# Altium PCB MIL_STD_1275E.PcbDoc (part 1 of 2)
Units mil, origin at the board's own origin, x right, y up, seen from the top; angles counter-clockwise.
Board outline 4000 x 3000 mil, 4 copper layers (Top Layer 1, GND, Signal Layer, Bottom Layer 1), stack 61.2 mil thick; 67 components, 20 nets, 127 pads, 432 vias.
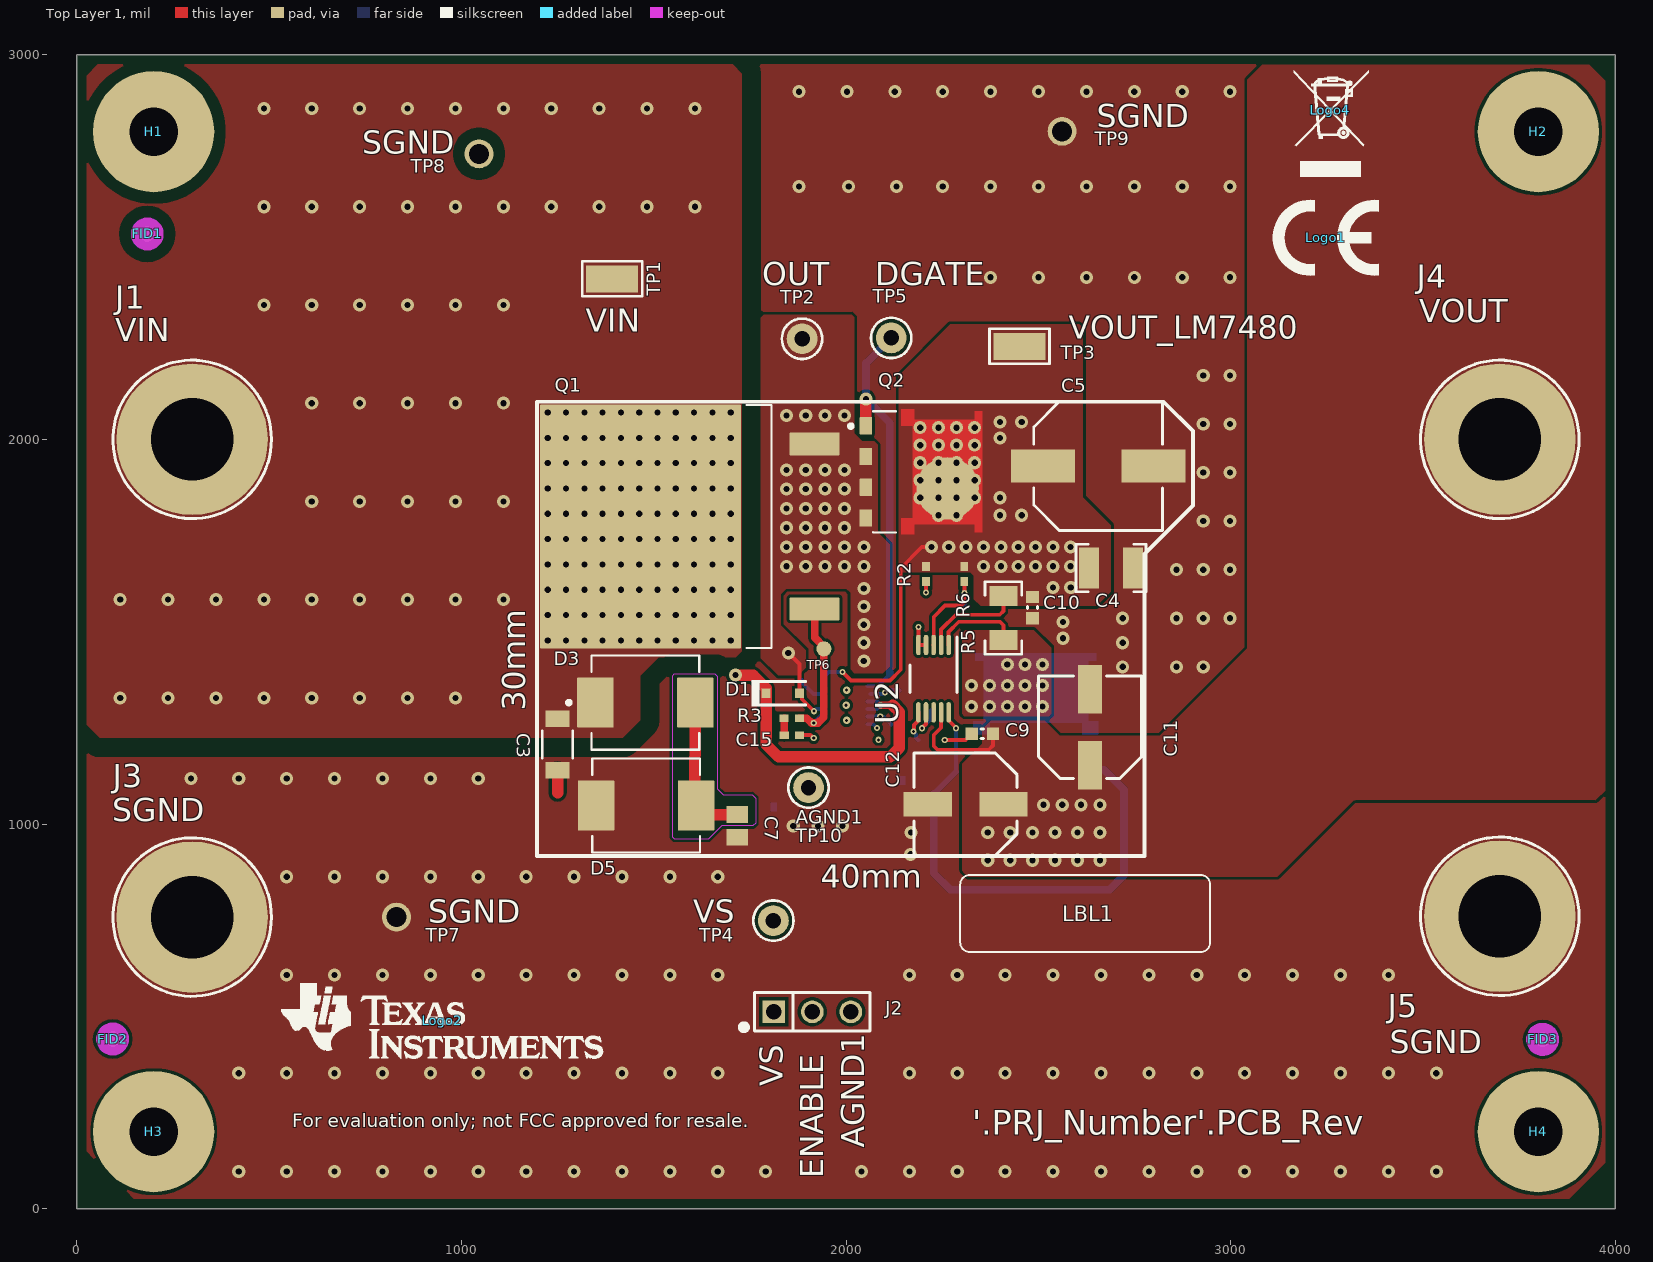
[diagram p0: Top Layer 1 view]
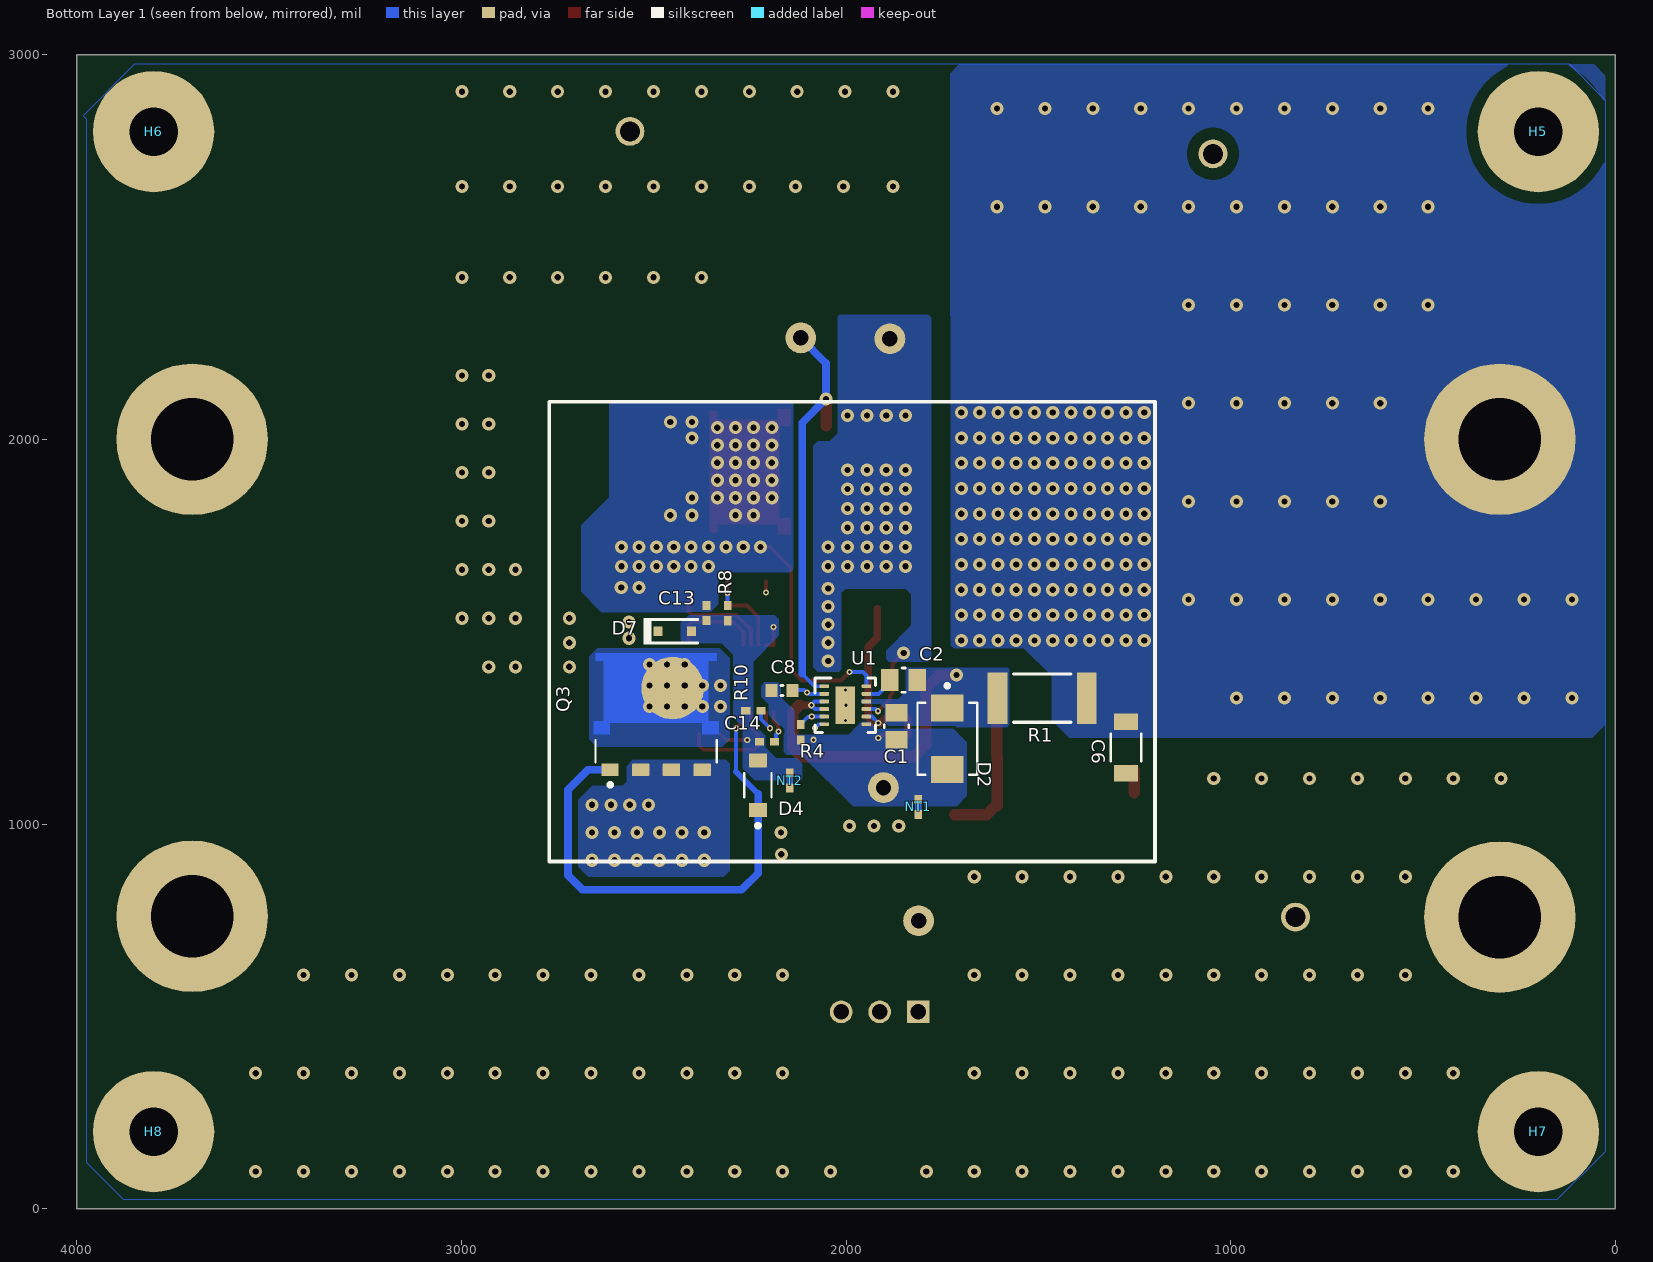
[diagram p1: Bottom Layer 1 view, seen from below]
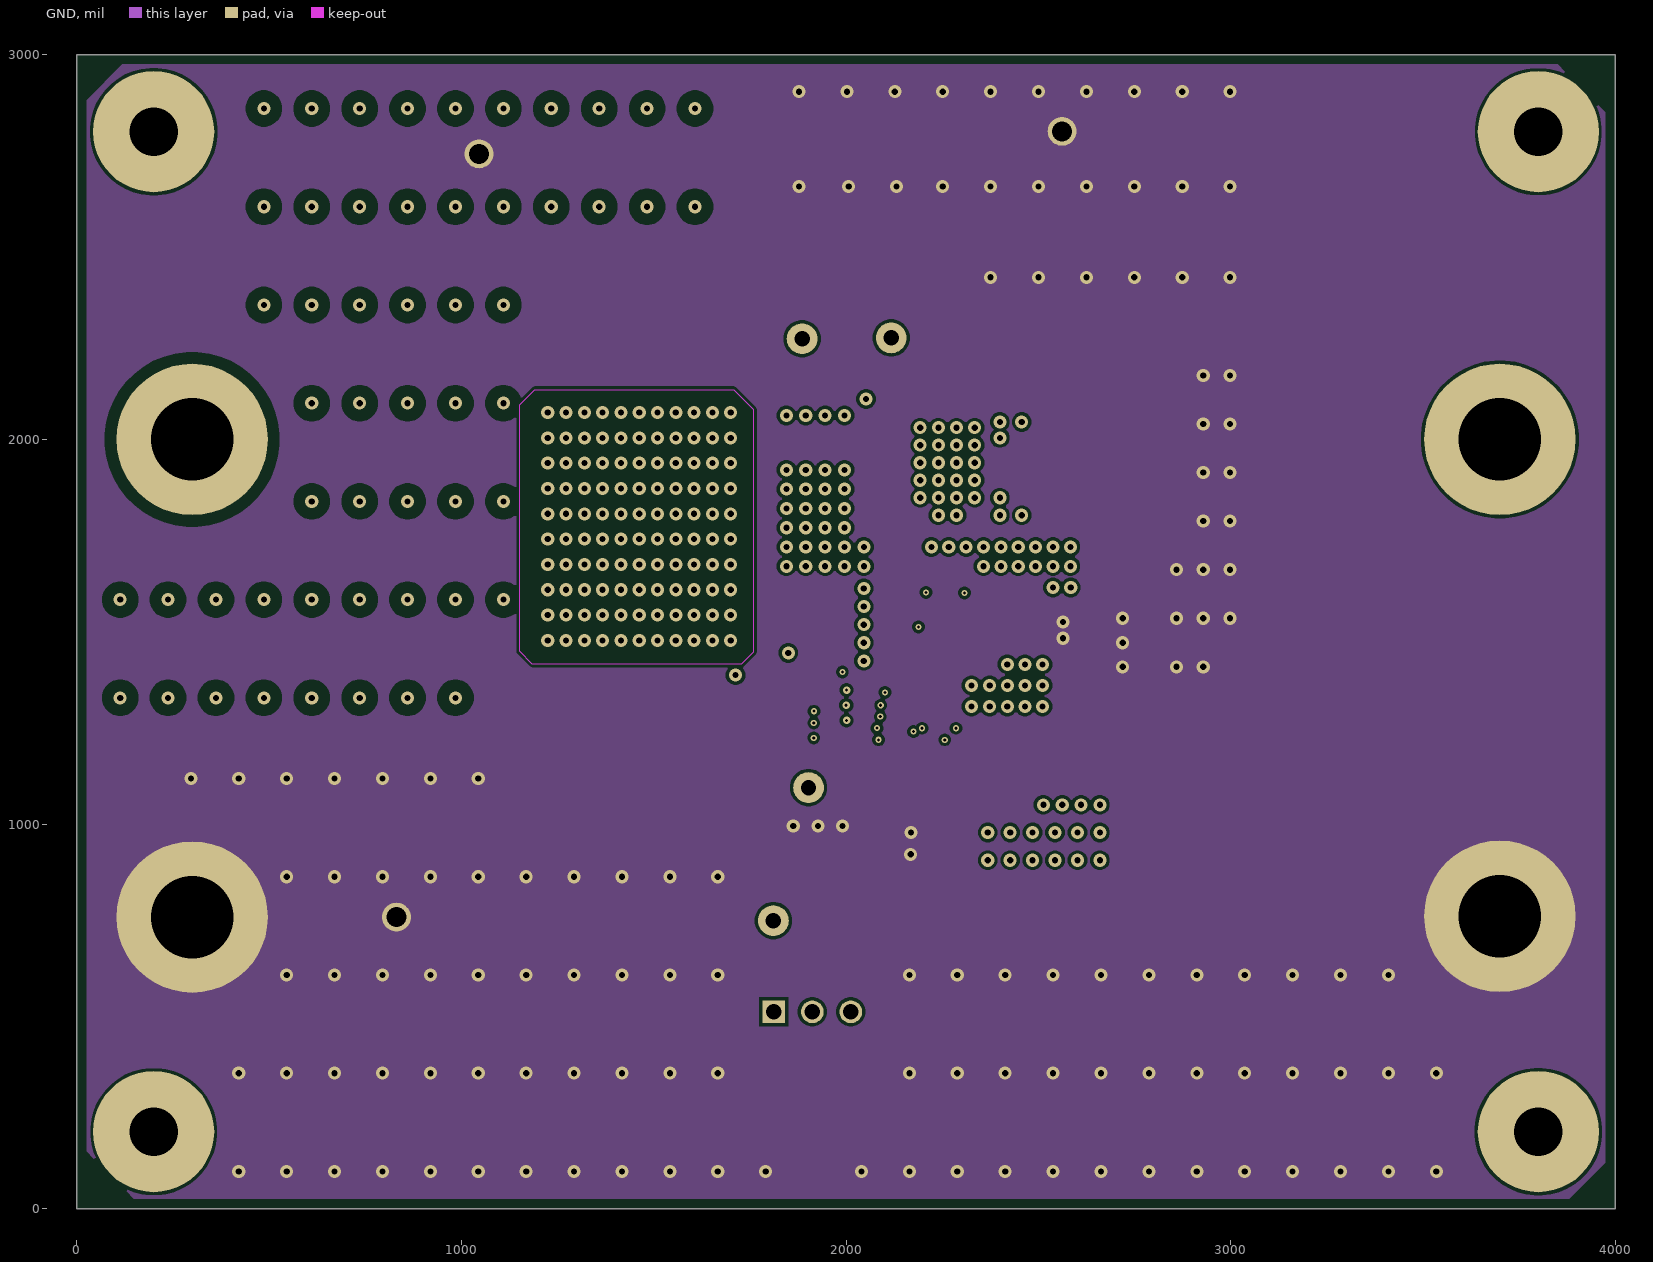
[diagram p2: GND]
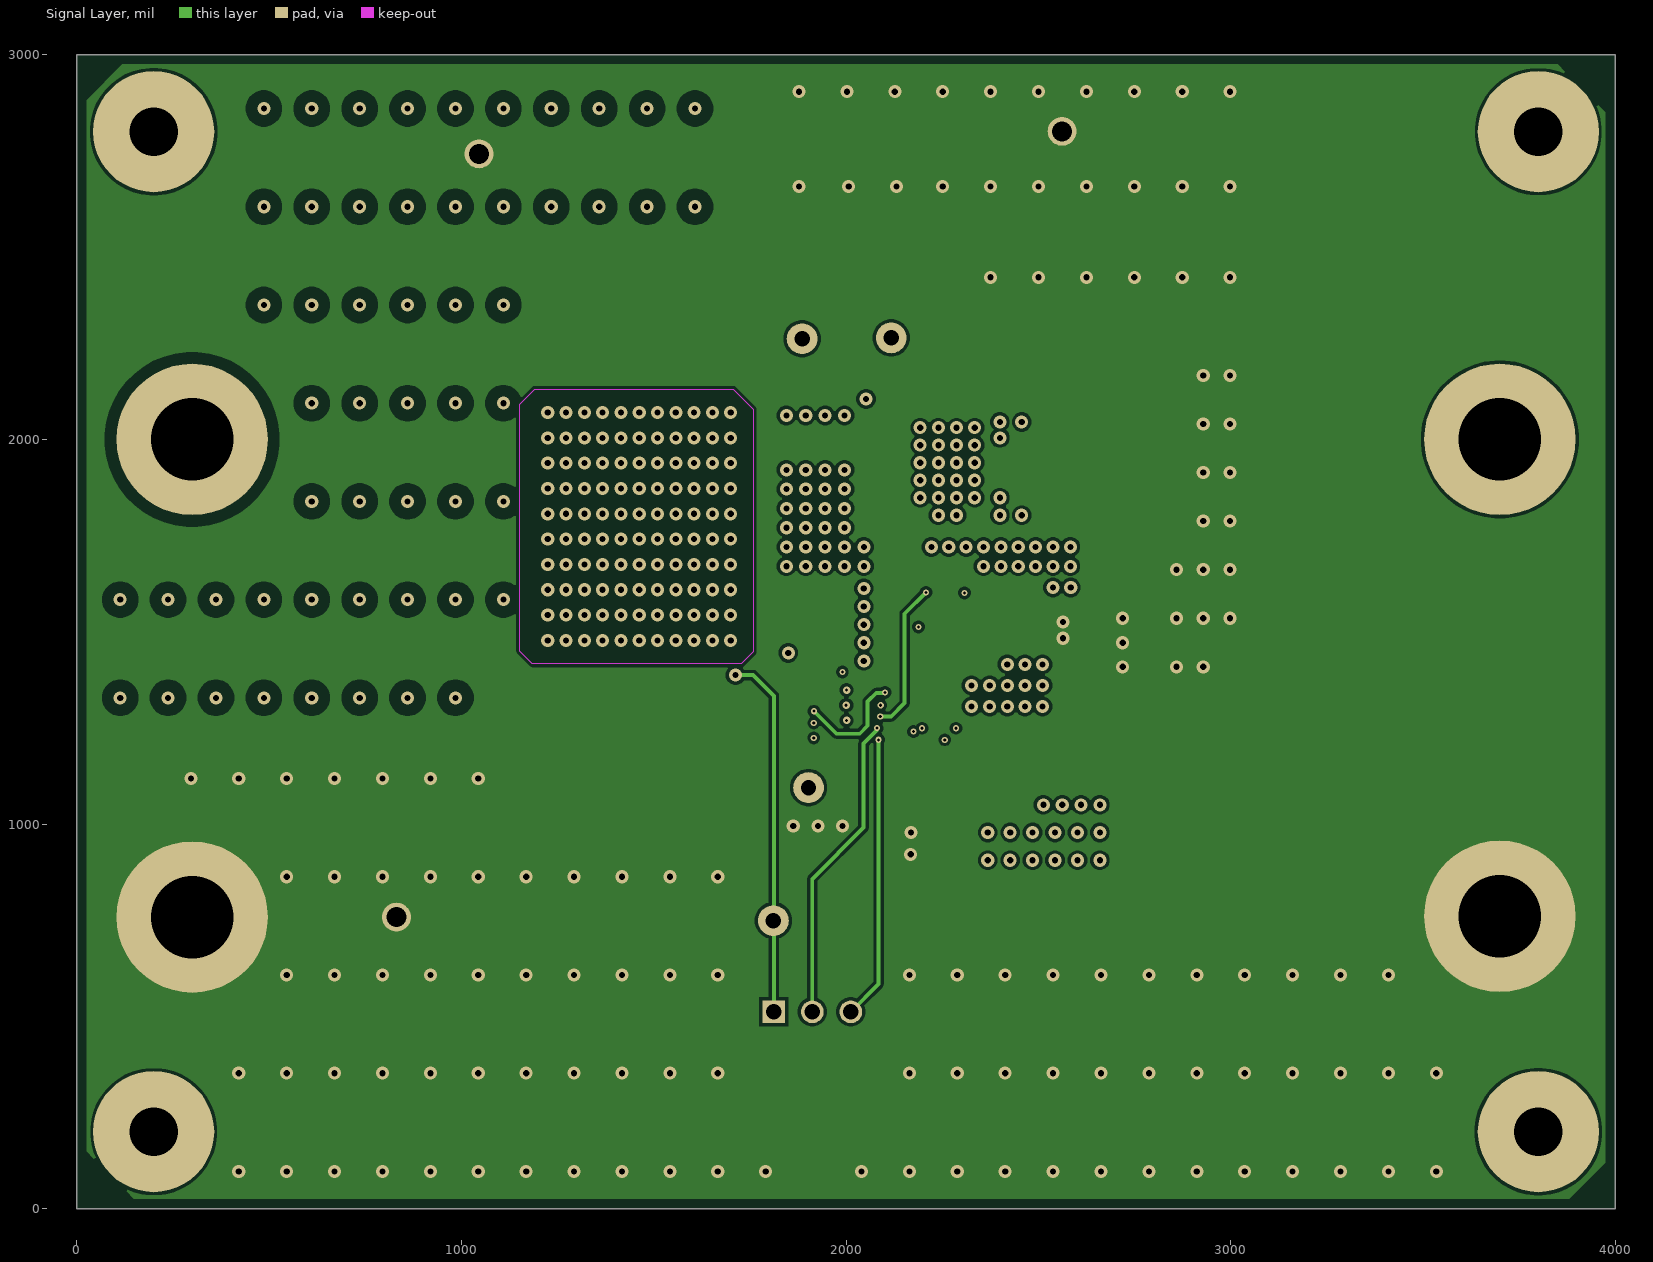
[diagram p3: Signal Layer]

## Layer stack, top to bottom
Top Solder: solder mask 0.4, Solder Resist, Dk 3.5
Top Layer 1: signal copper 1.378
Dielectric 1: prepreg 2.8, PP-006, Dk 4.1
GND: signal copper 1.4
Dielectric1: core 50.044, FR-4 High Tg, Dk 4.8
Signal Layer: signal copper 1.4
Dielectric 2: prepreg 2.8, PP-006, Dk 4.1
Bottom Layer 1: signal copper 1.378
Bottom Solder: solder mask 0.4, Solder Resist, Dk 3.5

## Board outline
0,0 4000,0 4000,3000 0,3000

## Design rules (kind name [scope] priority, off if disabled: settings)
AcuteAngle [All] p1: minimum=4.50000000000000E+0001 checktracksonly=FALSE
AssemblyTestPointUsage [All] p1: valid=2
BoardOutlineClearance BoardOutlineClearance_MountingHoles [OnCopper and InComponentClass('Mounting Holes')] p1: gap=39.37 ignorepadtopadclearanceinfootprint=FALSE
BoardOutlineClearance BoardOutlineClearance_Poly [OnCopper and IsPoly] p2: gap=25 ignorepadtopadclearanceinfootprint=FALSE
BoardOutlineClearance [OnCopper and Not InComponentClass('Logo') and not InComponentClass('FiducialMark') and not InRegion(1000,500,4000,800) and not InPoly] p3: gap=75 ignorepadtopadclearanceinfootprint=FALSE
Clearance Clear_Vin [InNet('VIN')] p1: gap=30 ignorepadtopadclearanceinfootprint=TRUE except(50: Fill-Fill Fill-Poly Fill-Region Poly-Poly Poly-Region Region-Region)
Clearance Clearance_MH [InPadClass('MH')] p2: gap=20 ignorepadtopadclearanceinfootprint=TRUE
Clearance Clearance_Keepouts [((IsTrack Or IsArc) And Not InPoly) And IsFree and IsKeepOut vs ((IsTrack Or IsArc) And Not InPoly) And IsFree and IsKeepOut] p3: gap=0 ignorepadtopadclearanceinfootprint=FALSE
Clearance Clearance_Poly [InPolygon] p4: gap=8 ignorepadtopadclearanceinfootprint=TRUE
Clearance Clearance_FiducialMark [IsKeepOut and InComponentClass('FiducialMark') vs IsPad and InComponentClass('FiducialMark')] p5: gap=0 ignorepadtopadclearanceinfootprint=FALSE
Clearance [All] p6: gap=8 ignorepadtopadclearanceinfootprint=TRUE except(20: Fill-Fill Fill-Poly Fill-Region Poly-Poly Poly-Region Region-Region)
ComponentClearance ComponentClearance_MountingHoles_FiducialMarks [InComponentClass('Mounting Holes') vs InComponentClass('FiducialMark')] p1: gap=50 collisioncheckmode=3 verticalgap=10 showdistances=FALSE
ComponentClearance ComponentClearance_Shunt [InComponentClass('Header') vs InComponentClass('Shunt')] p2: gap=0 collisioncheckmode=3 verticalgap=0 showdistances=FALSE
ComponentClearance ComponentClearance_Logo [InComponentClass('Logo')] p3: gap=50 collisioncheckmode=3 verticalgap=10 showdistances=FALSE
ComponentClearance ComponentClearance_ScrewToNut [(HasFootprint('NY PMS 440 0025 PH')) vs (HasFootprint('Keystone_1902C'))] p4: gap=5 collisioncheckmode=3 verticalgap=10 showdistances=FALSE
ComponentClearance ComponentClearance_MountingHoles [InComponentClass('Mounting Holes')] p5: gap=250 collisioncheckmode=3 verticalgap=100000 showdistances=FALSE
ComponentClearance ComponentClearance_SmallPassives [HasFootprint('0201*') or HasFootprint('0402*') or HasFootprint('0508') or HasFootprint('0603*') or HasFootprint('0612') or HasFootprint('0805*') or HasFootprint('0815*') or HasFootprint('0830*') or HasFootprint('1206*') or HasFootprint('1210*') or HasFootprint('1808*') or HasFootprint('1812*') or HasFootprint('1825*') or HasFootprint('2010*') or HasFootprint('2220*') or HasFootprint('2225*') or HasFootprint('2512*') or HasFootprint('2728*') or HasFootprint('3518*') vs HasFootprint('0201*') or HasFootprint('0402*') or HasFootprint('0508') or HasFootprint('0603*') or HasFootprint('0612') or HasFootprint('0805*') or HasFootprint('0815*') or HasFootprint('0830*') or HasFootprint('1206*') or HasFootprint('1210*') or HasFootprint('1808*') or HasFootprint('1812*') or HasFootprint('1825*') or HasFootprint('2010*') or HasFootprint('2220*') or HasFootprint('2225*') or HasFootprint('2512*') or HasFootprint('2728*') or HasFootprint('3518*')] p6: gap=14.96 collisioncheckmode=3 verticalgap=10 showdistances=FALSE
ComponentClearance ComponentClearance_THtoSMT [IsThruComponent vs IsSMTComponent] p7: gap=40 collisioncheckmode=3 verticalgap=30 showdistances=FALSE
ComponentClearance ComponentClearance_THtoTH [IsThruComponent vs IsThruComponent] p8: gap=30 collisioncheckmode=3 verticalgap=30 showdistances=FALSE
ComponentClearance [All] p9: gap=24 collisioncheckmode=3 verticalgap=10 showdistances=FALSE
DiffPairsRouting [All] p1: maxlimit=100 minlimit=10 mostfreqgap=10 toplayer_minwidth=15 toplayer_maxwidth=15 toplayer_prefwidth=15 midlayer1_minwidth=15 midlayer1_maxwidth=15 midlayer1_prefwidth=15 midlayer2_minwidth=15 midlayer2_maxwidth=15 midlayer2_prefwidth=15 bottomlayer_minwidth=15 bottomlayer_maxwidth=15 bottomlayer_prefwidth=15 maxuncoupledlength=1000
FabricationTestPointUsage TestPointUsage [All] p1: valid=2 allowmultiple=FALSE
FabricationTestpoint Testpoint [All] p1: side=3 testpointundercomponent=TRUE minsize=40 maxsize=100 preferedsize=60 minholesize=0 maxholesize=40 preferedholesize=32 testpointgrid=1 allowsidetop=TRUE allowsidebottom=TRUE usegrid=TRUE gridtolerance=0.01
FanoutControl Fanout_LCC [IsLCC] p1: bgadir=Out bgaviamode=Centered fanoutstyle=Auto fanoutdirection=Alternating viagrid=1 // Fanout_LCC (Default Rule)
FanoutControl Fanout_BGA [IsBGA] p2: bgadir=Out bgaviamode=Centered fanoutstyle=Auto fanoutdirection=Alternating viagrid=1 // Fanout_BGA (Default Rule)
FanoutControl Fanout_Default [All] p4: bgadir=Out bgaviamode=Centered fanoutstyle=Auto fanoutdirection=Alternating viagrid=1 // Fanout_Default (Default Rule)
FanoutControl Fanout_Small [(CompPinCount < 5)] p5: bgadir=Out bgaviamode=Centered fanoutstyle=Auto fanoutdirection=OutThenIn viagrid=1 // Fanout_Small (Default Rule)
HoleSize [All] p1: absolutevalues=TRUE maxlimit=251 minlimit=7.87 maxpercent=80.000 minpercent=20.000
MinimumAnnularRing MinimumAnnularRing_ThermalPadVias [IsVia and InAnyComponent] p1: minimumring=5.91
MinimumAnnularRing [All] p2: minimumring=4
MinimumSolderMaskSliver MinimumSolderMaskSliver_Logo [InComponentClass('Logo') vs InComponentClass('Logo')] p1: minsoldermaskwidth=0.7
MinimumSolderMaskSliver [All] p2: minsoldermaskwidth=3.94
PlaneConnect [All] p1: planeconnectstyle=Direct reliefexpansion=10 reliefentries=4 reliefconductorwidth=10 reliefairgap=10
PolygonConnect [All] p1: connectstyle=Direct reliefconductorwidth=10 reliefentries=4 polygonreliefangle="90 Angle" airgapwidth=10
RoutingVias ThermalPadVias [IsVia and InAnyComponent] p1: holewidth=7.87 width=19.68 viastyle="Through Hole" minholewidth=7.87 minwidth=19.68 maxholewidth=12.99 maxwidth=23.62
RoutingVias [All] p2: holewidth=16 width=34 viastyle="Through Hole" minholewidth=8 minwidth=16 maxholewidth=40 maxwidth=65
ShortCircuit U1 [InPadClass('U1') vs Hole] p1: allowed=TRUE
ShortCircuit [All] p2: allowed=FALSE
SilkToBoardRegionClearance [Not ((IsComment or IsDesignator) And (Hide <> 'False')) and not InRegion(1000,500,4000,800)] p1:
SilkToSilkClearance SilkToSilkClearance_Pb-FreeLogo [(HasFootprint('Pb-Free_Overlay_Medium') OR HasFootprint('Pb-Free_Overlay_Small')) vs (HasFootprint('Pb-Free_Overlay_Medium') OR HasFootprint('Pb-Free_Overlay_Small'))] p1: silktosilkclearance=0
SilkToSilkClearance [All] p2: silktosilkclearance=3.94
SilkToSolderMaskClearance SilkToComponentPadClearance [(IsPad or IsFill or IsRegion) and InAnycomponent] p1: minsilkscreentomaskgap=2 clearancetoexposedcopper=TRUE
SilkToSolderMaskClearance "Silk to Solder Mask Opening" [All] p2: minsilkscreentomaskgap=2 clearancetoexposedcopper=FALSE
SolderMaskExpansion SolderMaskExpansion_via [IsVia] p1: expansion=0 istentingtop=FALSE
SolderMaskExpansion SolderMaskExpansion_pads [ispad] p2: expansion=1.97 istentingtop=FALSE
UnRoutedNet [All] p1: checkbadconnections=TRUE
Width [All] p1: maxlimit=100 minlimit=6 preferedwidth=10 checkconnectedcopper=TRUE
13 further rules are at their usual default settings.

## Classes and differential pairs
component class MIL_STD_1275E_LM74800_Clamping_Circuit: C1 C2 C3 C4 C5 C6 C7 C8 C15 D1 D2 D3 D5 J1 J2 J3 NT1 Q1 Q2 R1 R2 R3 R4 TP1 TP2 TP3 TP4 TP5 TP6 TP7 TP8 TP9 TP10 U1
component class MIL_STD_1275E_LM5069_Clamping_Circuit: C9 C10 C11 C12 C13 C14 D4 D7 J4 J5 NT2 Q3 R5 R6 R8 R10 U2
component class Header: J2
component class "Mounting Holes": H1 H2 H3 H4
component class Logo: Logo2
component class MIL_STD_1275E_Hardware: FID1 FID2 FID3 H1 H2 H3 H4 H5 H6 H7 H8 LBL1 Logo1 Logo2 Logo3 Logo4
component class FiducialMark: FID1 FID2 FID3
component class Label: LBL1

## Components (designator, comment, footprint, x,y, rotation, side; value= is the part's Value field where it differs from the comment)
C1 "08051C105K4Z2A" 0805_150 1868.56,1254.28 r270 bottom value=1uF
C2 "08051C105K4Z2A" 0805_150 1850.38,1374.18 r0 bottom value=1uF
C3 "C3216X7T2W104M160AE" 1206_180 1249.99,1206.88 r270 top value=0.1uF
C4 "CMP-0009084-1" 1210_210 2688.98,1665.64 r0 top value=2.2uF
C5 "EMVE630ADA470MHA0G" CAPSMT_62_HA0 2655.81,1930.59 r0 top value=47uF
C6 "C3216X7T2W104M160AE" 1206_180 1272.17,1198.82 r270 bottom value=0.1uF
C7 "CGA4J3X7R1H105K125AB" 0805L 1717.28,995.02 r270 top value=1uF
C8 "CGA3E2X7R2A153K080AA" 0603L 2166.46,1346.98 r0 bottom value=0.015uF
C9 "C0603C104J5RACTU" 0603L 2354.46,1234.67 r180 top value=0.1uF
C10 "GRM188R72A104KA35D" 0603L 2484.67,1562.5 r270 top value=0.1uF
C11 "EEEFTH101XAP" Panasonic_D8 2634.37,1251.55 r90 top value=100uF
C12 "EEEFTH101XAP" Panasonic_D8 2311.11,1051.3 r180 top value=100uF
C13 "GRM155R72A102KA01D" 0402L 2362.74,1548.63 r90 bottom value=1000pF
C14 "GRM155R61A564KE15D" 0402L 2205.06,1214.07 r0 bottom value=0.56uF
C15 "CGA2B3X7S2A103K050BB" 0402L 1859.08,1231.17 r0 top value=0.01uF
D1 "1N4148WS-HG3-08" SOD-323 1835.46,1339.91 r0 top value=100V
D2 "SMBJ5369B-TP" FP-SMBJ5369B-TP_SMB-MFG 1736.6,1221.54 r270 bottom
D3 "SMDJ120A" FP-SMDJ120A_DO214AB-MFG 1478.3,1315.71 r0 top
D4 "SZMMSZ4715T1G" FP-SZMMSZ4715T1G_SOD123-MFG 2228.84,1100.98 r90 bottom
D5 "5.0SMDJ33CA" FP-5.0SMDJ33CA_DO214AB-MFG 1480.41,1048.09 r0 top
D7 "BAV20WS-TP" SOD-323 2445.32,1501.24 r180 bottom value=150V
FID1 "Fiducial" Fiducial10-20 183.21,2534.06 r0 top
FID2 "Fiducial" Fiducial10-20 93.21,440.98 r0 top
FID3 "Fiducial" Fiducial10-20 3811.24,439.96 r0 top
H1 "NY PMS 440 0025 PH" "NY PMS 440 0025 PH" 200,2800 r0 top
H2 "NY PMS 440 0025 PH" "NY PMS 440 0025 PH" 3800,2800 r0 top
H3 "NY PMS 440 0025 PH" "NY PMS 440 0025 PH" 200,200 r0 top
H4 "NY PMS 440 0025 PH" "NY PMS 440 0025 PH" 3800,200 r0 top
H5 "1902C" Keystone_1902C 200,2800 r180 bottom
H6 "1902C" Keystone_1902C 3800,2800 r180 bottom
H7 "1902C" Keystone_1902C 200,200 r180 bottom
H8 "1902C" Keystone_1902C 3800,200 r180 bottom
J1 "CMP-0055166-2" Keystone575-8 300,2000 r90 top
J2 "PEC03SAAN" CONN_PEC03SAAN 1912.43,511.6 r0 top
J3 "CMP-0055166-2" Keystone575-8 300,758 r90 top
J4 "CMP-0055166-2" Keystone575-8 3700,2000 r90 top
J5 "CMP-0055166-2" Keystone575-8 3700,760 r90 top
LBL1 "THT-14-423-10" Label_650x200 2621.92,767.3 r0 top
Logo1 "CE Mark" CE_Mark_5mm 3247.82,2524.21 r0 top
Logo2 "Texas Instruments" TI_Stacked_Overlay_Small 949.88,488.24 r0 top
Logo3 "FCC disclaimer" FCC_disclaimer 2350,3380 r0 top
Logo4 "WEEE logo" WEEE_Minimum 3259.19,2855.52 r0 top
NT1 "Net-Tie" NetTie_0402 1812.43,1044.24 r90 bottom net-tie
NT2 "Net-Tie" NetTie_0402 2145.93,1113.08 r90 bottom net-tie
Q1 "IXTT88N30P" FP-IXTT88N30P_TO-268AA-IPC_C 1593.59,1773.6 r90 top
Q2 "SQJQ466E-T1_GE3" "FP-SQJQ466E-T1_GE3_PowerPAK 8 x 8L-MFG" 2194.88,1915.52 r270 top
Q3 "SQJQ466E-T1_GE3" "FP-SQJQ466E-T1_GE3_PowerPAK 8 x 8L-MFG" 2493.79,1284.21 r180 bottom
R1 "HVCB2512FDD10K0" 2512_084 1489.8,1327.55 r180 bottom value=10.0k
R2 "ERJ-2RKF1003X" 0402L 2208.03,1650.32 r90 top value=100k
R3 "CRCW0402100RJNED" 0402L 1858.95,1274.97 r180 top value=100
R4 "CRCW04022K55FKED" 0402L 2117.24,1238.56 r90 bottom value=2.55k
R5 "CRF1206-FZ-R004ELF" 1206 2409.15,1535.66 r270 top value=0.004
R6 "CRCW040295K3FKED" 0402L 2307.9,1650.32 r90 top value=95.3k
R8 "CRCW040213K7FKED" 0402L 2307.9,1548.12 r90 bottom value=13.7k
R10 "CRCW040254K9FKED" 0402L 2240.88,1294.74 r180 bottom value=54.9k
TP1 "5015" Testpoint_Keystone_Miniature 1391.85,2417.46 r180 top
TP2 "5003" Keystone5003 1885.81,2261.6 r180 top
TP3 "5015" Testpoint_Keystone_Miniature 2450.88,2241.48 r180 top
TP4 "5003" Keystone5003 1811.24,748.77 r180 top
TP5 "5003" Keystone5003 2117.53,2263.8 r180 top
TP6 "TP_SM_1MM" TP_SM_1MM 1942.53,1455.45 r180 top
TP7 "CMP-0055161-1" CONN_1040 831.24,758 r90 top
TP8 "CMP-0055161-1" CONN_1040 1045.86,2742.33 r90 top
TP9 "CMP-0055161-1" CONN_1040 2561.81,2800.96 r90 top
TP10 "5001" Keystone5001 1902.53,1094.66 r180 top
U1 "PLM74800DRRRQ1" DRR0012E 2001.59,1308.76 r180 bottom
U2 "LM5069MM-2" DGS0010A_N 2227.71,1377.84 r270 top

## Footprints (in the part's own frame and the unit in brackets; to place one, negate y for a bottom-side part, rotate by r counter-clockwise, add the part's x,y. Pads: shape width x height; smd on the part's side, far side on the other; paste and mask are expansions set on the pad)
0402L [mm] "0402 from SM-752 data"
  rect 0.6x0.5 smd: 1(-0.5,0) 2(0.5,0)
  body extent -0.55,-0.3 0.55,0.3, height 0.6
0603L [mm] "0603 from SM-752 data"
  rect 0.8x0.85 smd: 1(-0.7,0) 2(0.7,0)
  silkscreen extent -0.07,-0.33 0.07,0.33, body extent -0.87,-0.47 0.87,0.47, height 1
0805_150 [mm] "0805 / 1.5 mm height"
  rect 1.15x1.45 smd: 1(-0.9,0) 2(0.9,0)
  silkscreen extent -0.1,-0.8 0.1,0.8, body extent -1.1,-0.72 1.1,0.72, height 1.5
0805L [mm] "0805 from SM-752 data"
  rect 1.1x1.4 smd: 1(-0.75,0) 2(0.75,0)
  body extent -1.1,-0.72 1.1,0.72, height 1.45
1206 [mm] "1206 from SM-752 data"
  rect 1.3x1.85 smd: 1(-1.45,0) 2(1.45,0)
  silkscreen extent -2.4,-1.21 2.4,1.21, body extent -1.7,-0.9 1.7,0.9, height 1.35
1206_180 [mm] "1206_180"
  rect 1.1x1.6 smd: 1(-1.7,0) 2(1.7,0)
  silkscreen extent -0.9,-1 0.9,1, body extent -1.75,-0.95 1.75,0.95, height 1.8
1210_210 [mm] "1210"
  rect 1.3x2.7 smd: 1(-1.45,0) 2(1.45,0)
  silkscreen extent -2.32,-1.57 2.32,1.57, body extent -1.7,-1.35 1.7,1.35, height 2.1
2512_084 [mm] "Chip Resistor, Body 6.3x3.2mm"
  rect 1.3x3.4 smd: 1(-2.95,0) 2(2.95,0)
  silkscreen extent -1.9,-1.6 1.9,1.6, body extent -3.22,-1.67 3.22,1.67, height 0.84
CAPSMT_62_HA0 [mm] "8 x 10mm:  Chemi-Con HA0"
  rect 4.2x2.2 smd: 1(-3.65,0) 2(3.65,0)
  silkscreen extent -4.25,-4.25 4.25,4.25, body extent -4.25,-4.25 4.25,4.25, height 10.5
CE_Mark_5mm [mil] "Minimum text height for CE Mark"
  silkscreen extent -138,-98 138,98
CONN_1040 [mil] "Test Point, PC  test point Terminal"
  round 75 hole 52: 1(0,0)
  body extent -55,-12 55,13, height 276
CONN_PEC03SAAN [mm] "SULLINS"
  rect 1.5x1.5 hole 1.016: 1(-2.54,0)
  round 1.5 hole 1.016: 2(0,0) 3(2.54,0)
  silkscreen extent -4.72,-1.27 3.81,1.27, body extent -3.84,-1.3 3.84,1.3, height 8.38
DGS0010A_N [mm] "TSSOP, 10-Leads, Body 3x3mm, Pitch 0.5mm, IPC Medium Density"
  oval 1.35x0.3 smd: 1(-2.225,1) 2(-2.225,0.5) 3(-2.225,0) 4(-2.225,-0.5) 5(-2.225,-1) 6(2.225,-1) 7(2.225,-0.5) 8(2.225,0) 9(2.225,0.5) 10(2.225,1)
  silkscreen extent -2.75,-1.55 0.9,1.55, body extent -2.45,-1.5 2.45,1.5, height 0.96
DRR0012E [mm] "WSON-12"
  rrect40% 0.62x0.25 smd: 1(-1.39,1.25) 2(-1.39,0.75) 3(-1.39,0.25) 4(-1.39,-0.25) 5(-1.39,-0.75) 6(-1.39,-1.25) 7(1.39,-1.25) 8(1.39,-0.75) 9(1.39,-0.25) 10(1.39,0.25) 11(1.39,0.75) 12(1.39,1.25)
  rrect8% 1.3x2.5 smd paste-1.7: 13(0,0)
  silkscreen extent -2,-1.8 2,1.8, body extent -1.5,-1.5 1.5,1.5, height 0.81
FCC_disclaimer [mil]
Fiducial10-20 [mm]
  round 1 smd mask+0.5: 1(0,0)
  Top Layer 1 keep-out circle w1.178: c0,0 r0.5
FP-5.0SMDJ33CA_DO214AB-MFG [mm]
  rrect4% 2.4x3.3 smd paste+0 mask+0: 1(-3.3,0) 2(3.3,0)
  silkscreen extent -3.55,-3.11 3.55,3.11, body extent -4.6,-3.21 4.6,3.21, height 0.25
FP-IXTT88N30P_TO-268AA-IPC_C [mm]
  rrect7% 1.5x3.3 smd paste+0 mask+0: 1(-5.45,-8.25) 3(5.45,-8.25)
  rrect1% 16.1x13.3 smd paste+0 mask+0: 4(0,3.25)
  silkscreen extent -8.03,-5.4 8.03,-3.77, body extent -8.15,-10 8.15,10, height 0.25
FP-SMBJ5369B-TP_SMB-MFG [mil]
  rrect6% 70x85 smd paste+0 mask+0: 1(-80,0) 2(80,0)
  silkscreen extent -143,-78 94,78, body extent -105,-71 105,71, height 95
FP-SMDJ120A_DO214AB-MFG [mm]
  rrect4% 2.4x3.3 smd paste+0 mask+0: 1(-3.3,0) 2(3.3,0)
  silkscreen extent -5.17,-3.11 3.55,3.11, body extent -4.6,-3.21 4.6,3.21, height 0.25
"FP-SQJQ466E-T1_GE3_PowerPAK 8 x 8L-MFG" [mm]
  rrect12% 1.15x0.82 smd paste+0 mask+0: 1(-3.045,-3.64) 2(-1.015,-3.64) 3(1.015,-3.64) 4(3.045,-3.64)
  round 4.13 smd paste+0 mask+0: 5(1.09,1.755)
  Top Layer 1 region: -4,4.05 4,4.05 4,3.55 3.45,3.55 3.45,-0.44 4.125,-0.44 4.125,-1.29 3.055,-1.29 3.055,-0.54 -3.055,-0.54 -3.055,-1.29 -4.125,-1.29 -4.125,-0.44 -3.45,-0.44 -3.45,3.55 -4,3.55 -4,4.05
  silkscreen extent -4,-4.75 4,-1.67, body extent -4.23,-4.15 4.23,4.15, height 0.25
FP-SZMMSZ4715T1G_SOD123-MFG [mil]
  rrect11% 36x48 smd paste+0 mask+0: 1(-64.5,0) 2(64.5,0)
  silkscreen extent -110,-35 32,35, body extent -72,-31 72,31, height 53
Keystone575-8 [mm] "Banana Jack"
  round 10 hole 5.45: 1(0,0)
  silkscreen extent -5.23,-5.23 5.23,5.23, body extent -3.92,-3.94 3.95,3.94, height 2.36
Keystone5001 [mil] "For Keystone 500x miniature loop terminals"
  round 80 hole 40: 1(0,0)
  silkscreen extent -52,-52 52,52, body extent -49,-49 49,49, height 182
Keystone5003 [mil] "For Keystone 500x miniature loop terminals"
  round 80 hole 40: 1(0,0)
  silkscreen extent -52,-52 52,52, body extent -49,-49 49,49, height 182
Keystone_1902C [mil] "Hex Standoff, 4-40 threaded, nylon"
  round 1 on Mech4: 0(0,0)
  body extent -145,-126 146,126, height 501
Label_650x200 [mil] "Thermal Transfer Label"
  round 1 on Mech13: 0(0,0)
  silkscreen extent -325,-100 325,100, body extent -325,-100 325,100, height 1
NetTie_0402 [mm] "Net Tie 0402 size"
  rect 0.6x0.5 smd paste-0.5: 1(-0.5,0) 2(0.5,0)
  Top Layer 1 region: -0.279,0.203 0.279,0.203 0.279,-0.203 -0.279,-0.203
"NY PMS 440 0025 PH" [mm] "4-40 nylon screw and mounting hole"
  round 8 hole 3.2: 1(0,0)
  body extent -3.3,-3.3 3.3,3.3, height 2.69
Panasonic_D8 [mm] "SMD, 2-Leads, Dia 6.3mm"
  rect 3.2x1.6 smd: 1(-2.5,0) 2(2.5,0)
  silkscreen extent -3.4,-3.4 3.4,3.4, body extent -3.4,-3.4 3.4,3.4, height 8.01
SOD-323 [mm] "NXP recommended land pattern"
  rect 0.6x0.6 smd paste-0.05: 1(-1.1,0) 2(1.1,0)
  silkscreen extent -2.06,-0.86 1.53,0.86, body extent -1.3,-0.67 1.3,0.68, height 1.1
Testpoint_Keystone_Miniature [mil] "Miniature SMT test point"
  rect 135x70 smd: 1(0,0)
  silkscreen extent -78,-46 78,45, body extent -52,-20 52,20, height 61
TI_Stacked_Overlay_Small [mil]
  silkscreen extent -418,-98 418,98
TP_SM_1MM [mm] "1mm Test Point, SMT"
  round 1 smd paste-0.5: 1(0,0)
WEEE_Minimum [mil] "WEEElie bin"
  silkscreen extent -95,-172 99,104

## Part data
C1 C2: library part CMP-0861070-1, "CAP, CERM, 1 µF, 100 V,+/- 10%, X7R, AEC-Q200 Grade 1, 0805", Cap_Case=0805, Manufacturer=AVX, TempCo=X7R, Tolerance_%=10%, Value2=100V, ValueDisplayed=1µF
C3 C6: library part CMP-0008730-2, "CAP, CERM, 0.1 uF, 450 V, +/- 20%, X7T, 1206", Cap_Case=1206, Manufacturer=TDK, Supplier Part Number 1=445-6821-1-ND, TempCo=X7T, Tolerance_%=20%, Value1=Unknown, Value2=450V, ValueDisplayed=0.1uF
C4: "CAP, CERM, 2.2 uF, 100 V, +/- 10%, X7R, 1210", Cap_Case=1210, Manufacturer=Kemet, PartNumber=C1210C225K1RACTU, Supplier Part Number 1=399-5511-2-ND, TempCo=X7R, Tolerance_%=10%, Value1=Unknown, Value2=100V, ValueDisplayed=2.2uF
C5: library part CMP-0011301-2, "CAP, AL, 47 uF, 63 V, +/- 20%, SMD", Cap_Case=HA0, Manufacturer=Chemi-Con, Supplier Part Number 1=565-2267-1-ND, Tolerance_%=20%, Value1=Unknown, Value2=63V, ValueDisplayed=47uF
C7: library part CMP-0007976-2, "CAP, CERM, 1 uF, 50 V, +/- 10%, X7R, AEC-Q200 Grade 1, 0805", Cap_Case=0805, Manufacturer=TDK, Supplier Part Number 1=445-6961-1-ND, TempCo=X7R, Tolerance_%=10%, Value1="0.008782 ohm", Value2=50V, ValueDisplayed=1uF
C8: library part CMP-0007084-4, "CAP, CERM, 0.015 uF, 100 V, +/- 10%, X7R, AEC-Q200 Grade 1, 0603", Cap_Case=0603, Manufacturer=TDK, Supplier Part Number 1=445-5813-1-ND, TempCo=X7R, Tolerance_%=10%, Value1="0.128703 ohm", Value2=100V, ValueDisplayed=0.015uF
C9: library part CMP-0006858-4, "CAP, CERM, 0.1 uF, 50 V, +/- 5%, X7R, 0603", Cap_Case=0603, Manufacturer=Kemet, Supplier Part Number 1=399-7844-1-ND, TempCo=X7R, Tolerance_%=5%, Value1=Unknown, Value2=50V, ValueDisplayed=0.1uF
C10: library part CMP-0007469-4, "CAP, CERM, 0.1 uF, 100 V, +/- 10%, X7R, 0603", Cap_Case=0603, Manufacturer=MuRata, Supplier Part Number 1=490-3285-1-ND, TempCo=X7R, Tolerance_%=10%, Value1=Unknown, Value2=100V, ValueDisplayed=0.1uF
C11 C12: library part CMP-0011205-1, "CAP, AL, 100 uF, 50 V, +/- 20%, 0.34 ohm, AEC-Q200 Grade 2, SMD", Cap_Case=6.3x7.7mm, Manufacturer=Panasonic, Supplier Part Number 1=PCE5024CT-ND, Tolerance_%=20%, Value1="0.34 ohm", Value2=50V, ValueDisplayed=100uF
C13: library part CMP-0006699-1, "CAP, CERM, 1000 pF, 100 V, +/- 10%, X7R, 0402", Cap_Case=0402, Manufacturer=MuRata, Supplier Part Number 1=GRM155R72A102KA01D-ND, TempCo=X7R, Tolerance_%=10%, Value1=Unknown, Value2=100V, ValueDisplayed=1000pF
C14: library part CMP-0006584-2, "CAP, CERM, 0.56 uF, 10 V, +/- 10%, X5R, 0402", Cap_Case=0402, Manufacturer=MuRata, Supplier Part Number 1=GRM155R61A564KE15D-ND, TempCo=X5R, Tolerance_%=10%, Value1=Unknown, Value2=10V, ValueDisplayed=0.56uF
C15: library part CMP-0006333-2, "CAP, CERM, 0.01 uF, 100 V, +/- 10%, X7S, AEC-Q200 Grade 1, 0402", Cap_Case=0402, Manufacturer=TDK, Supplier Part Number 1=445-6910-1-ND, TempCo=X7S, Tolerance_%=10%, Value1="0.410191 ohm", Value2=100V, ValueDisplayed=0.01uF
D1: library part CMP-0860225-1, "Diode, Switching, 100 V, 150 A, AEC-Q101, SOD-323", Manufacturer=Vishay-Semiconductor, Value1=150A, Value2=1.2V
D2: library part CMP-0095181-1, "Zener Diode 51 V 5 W ±5% Surface Mount DO-214AA (SMB)", Digikey Part Number=SMBJ5369B-TPMSCT-ND, Forward Current=1mA, Manufacturer=MCC, Mouser Part Number=833-SMBJ5369B-TP, Operating Temperature Range="-55°C to +150°C", Power_W=5W
D3: library part CMP-0093492-1, "Diode TVS Single Uni-Dir 120V 3KW 2-Pin DO-214AB", Breakdown Voltage=133V, Clamping Voltage=193V, Digikey Part Number=SMDJ120ACT-ND, Manufacturer="Littelfuse Inc", Mouser Part Number=576-SMDJ120A, Operating Temperature Range="-65°C to +150°C"
D4: library part CMP-0094040-1, "Zener Diode 36 V 500 mW - Surface Mount SOD-123", Digikey Part Number=SZMMSZ4715T1GOSCT-ND, Manufacturer="On Semiconductor", Max Reverse Leakage Current=0.01uA, Mouser Part Number=863-SZMMSZ4715T1G, Operating Temperature Range="-55°C to +150°C", Power_W=500mW
D5: library part CMP-0093617-1, "53.3V Clamp 93.9A Ipp Tvs Diode Surface Mount DO-214AB (SMCJ)", Breakdown Voltage=36.7V, Clamping Voltage=53.3V, Digikey Part Number=F4120CT-ND, Manufacturer=Littelfuse, Mouser Part Number=652-5.0SMDJ33CA, Operating Temperature Range="-65°C to +150°C"
D7: library part CMP-0029044-2, "Diode, P-N, 150 V, 0.2 A, SOD-323", Manufacturer="Micro Commercial Components", Value1=0.2A, Value2=1.25V
FID1 FID2 FID3: library part CMP-0077181-1, "Fiducial mark.  There is nothing to buy or mount.", Manufacturer=N/A
H1 H2 H3 H4: library part CMP-0003617-1, "Machine Screw, Round, #4-40 x 1/4, Nylon, Philips panhead", Manufacturer="B&F Fastener Supply", Supplier Part Number 1=H542-ND
H5 H6 H7 H8: library part CMP-0003610-1, "Standoff, Hex, 0.5\"L #4-40 Nylon", Manufacturer=Keystone, Supplier Part Number 1=36-1902C-ND
J1 J3 J4 J5: "Standard Banana Jack, Uninsulated, 8.9mm", Manufacturer=Keystone, PartNumber=575-8, Supplier Part Number 1=36-575-8-ND
J2: library part CMP-0002338-1, "Header, 100mil, 3x1, Tin, TH", Color=Black, Current_A=3A, Manufacturer="Sullins Connector Solutions", Supplier Part Number 1=S1012E-03-ND, Voltage_V=1.8kV
LBL1: library part CMP-0003625-1, "Thermal Transfer Printable Labels, 0.650\" W x 0.200\" H - 10,000 per roll", Manufacturer=Brady, Supplier Part Number 1=97C5133
Logo1: library part CMP-0074844-1
Logo2: library part CMP-0074838-1, "Texas Instrument Corporate Signature"
Logo3: library part CMP-0074847-1, "FCC_disclaimer"
Logo4: library part CMP-0074769-1
NT1 NT2: library part CMP-0078142-4, "Single point connection between nets.", Manufacturer=N/A
Q1: library part CMP-0093697-1, "N-Channel 300 V 88A (Tc) 600W (Tc) Surface Mount TO-268AA", Digikey Part Number=IXTT88N30P-ND, Drain To Source Breakdown Voltage=300V, Input Capacitace At Vds="6300pF @ 25V", Manufacturer=Littlefuse, Mouser Part Number=747-IXTT88N30P, Operating Temperature Range="-55°C to +150°C", Power_W=600W, Pulse Drain Current=220A
Q2 Q3: library part CMP-0093493-1, "N-Channel 60 V 200A (Tc) 150W (Tc) Surface Mount PowerPAK® 8 x 8", Digikey Part Number=SQJQ466E-T1_GE3CT-ND, Drain To Source Breakdown Voltage=60V, Input Capacitace At Vds="8170pF @ 25V", Manufacturer=Vishay, Mouser Part Number=78-SQJQ466E-T1_GE3, Operating Temperature Range="-55°C to +175°C", Power_W=150W, Pulse Drain Current=500A, Typ Forward Diode Voltage=0.82V
R1: library part CMP-0015824-1, "RES, 10.0 k, 1%, 2 W, 2512", Manufacturer="Stackpole Electronics Inc", Power_W=2W, Supplier Part Number 1=HVCB2512FDD10K0CT-ND, TempCo="100 ppm/C", Tolerance_%=1%, Value_Code=10k0, ValueDisplayed=10.0k
R2: library part CMP-0026659-2, "RES, 100 k, 1%, 0.1 W, 0402", Manufacturer=Panasonic, Power_W=100mW, TempCo="100 ppm/C", Tolerance_%=1%, Value2=0.1W, Value_Code=100k
R3: library part CMP-0026824-3, "RES, 100, 5%, 0.063 W, AEC-Q200 Grade 0, 0402", Manufacturer=Vishay-Dale, Power_W=63mW, Supplier Part Number 1=541-100JCT-ND, TempCo="200 ppm/C", Tolerance_%=5%, Value2=0.063W, Value_Code=100R, ValueDisplayed=100
R4: library part CMP-0026238-2, "RES, 2.55 k, 1%, 0.063 W, AEC-Q200 Grade 0, 0402", Manufacturer=Vishay-Dale, Power_W=63mW, Supplier Part Number 1=541-2.55KLCT-ND, TempCo="100 ppm/C", Tolerance_%=1%, Value2=0.063W, Value_Code=2k55, ValueDisplayed=2.55k
R5: library part CMP-0078823-1, "RES, 0.004, 1%, 1 W, AEC-Q200 Grade 0, 1206", Manufacturer=Bourns, Power_W=1W, TempCo="50 ppm/C", Tolerance_%=1%, Value_Code=4L000, ValueDisplayed=0.004
R6: library part CMP-0026613-3, "RES, 95.3 k, 1%, 0.063 W, AEC-Q200 Grade 0, 0402", Manufacturer=Vishay-Dale, Power_W=63mW, Supplier Part Number 1=541-95.3KLCT-ND, TempCo="100 ppm/C", Tolerance_%=1%, Value2=0.063W, Value_Code=95k3, ValueDisplayed=95.3k
R8: library part CMP-0026005-3, "RES, 13.7 k, 1%, 0.063 W, AEC-Q200 Grade 0, 0402", Manufacturer=Vishay-Dale, Power_W=63mW, Supplier Part Number 1=541-13.7KLCT-ND, TempCo="100 ppm/C", Tolerance_%=1%, Value2=0.063W, Value_Code=13k7, ValueDisplayed=13.7k
R10: library part CMP-0026449-2, "RES, 54.9 k, 1%, 0.063 W, AEC-Q200 Grade 0, 0402", Manufacturer=Vishay-Dale, Power_W=63mW, Supplier Part Number 1=541-54.9KLCT-ND, TempCo="100 ppm/C", Tolerance_%=1%, Value2=0.063W, Value_Code=54k9, ValueDisplayed=54.9k
TP1 TP3: "Test Point, Miniature, SMT", Manufacturer=Keystone, Supplier Part Number 1=36-5015TR-ND
TP2 TP4 TP5: library part CMP-0055140-1, "Test Point, Miniature, Orange, TH", Color=Orange, Manufacturer=Keystone, Supplier Part Number 1=36-5003-ND
TP6: library part CMP-0003825-1, "1mm Test Point, SMT", Manufacturer=Any
TP7 TP8 TP9: "TEST POINT SLOTTED .118\", TH", Manufacturer=Keystone, PartNumber=1040, Supplier Part Number 1=36-1040-ND
TP10: library part CMP-0055138-1, "Test Point, Miniature, Black, TH", Color=Black, Manufacturer=Keystone, Supplier Part Number 1=36-5001-ND
U1: library part CMP-0860384-3, "Ideal Diode Controller with Load Dump Protection, DRR0012E (WSON-12)", Alternate Manufacturer="Texas Instruments"
U2: library part CMP-0071870-1, "Positive High Voltage Hot Swap / Inrush Current Controller with Power Limiting, 10-pin MSOP", Manufacturer="Texas Instruments", PackageTopMarking=ZXTT*SNBB, PowerWise=N

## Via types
v1: diameter 34, hole 16, Top Layer 1 to Bottom Layer 1, 391 vias
v2: diameter 34, hole 16, Top Layer 1 to Bottom Layer 1, tented both sides, 20 vias
v3: diameter 16, hole 8, Top Layer 1 to Bottom Layer 1, tented both sides, 16 vias
v4: diameter 19.68, hole 7.87, Top Layer 1 to Bottom Layer 1, 3 vias
v5: diameter 34, hole 16, Top Layer 1 to Bottom Layer 1, tented top, 2 vias

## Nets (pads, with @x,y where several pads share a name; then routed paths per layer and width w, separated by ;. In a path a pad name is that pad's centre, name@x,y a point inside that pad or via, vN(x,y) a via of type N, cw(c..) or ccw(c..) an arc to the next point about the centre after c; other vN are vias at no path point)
AGND1: C1.2 C8.2 C15.2 D2.2 J2.3 NT1.2 R4.1 TP10.1 U1.7 | length 777.7
  Top Layer 1 w10: C15.2@1878.76,1231.17 1907.24,1231.17 1914.72,1223.69 v3(1916.1,1223.69)
  Signal Layer w10: J2.3@2012.43,511.6 2084.9,584.07 2084.9,1106.9 v3(2084.9,1218.88)
AGND2: C9.2 C13.1 C14.2 D4.2 D7.2 NT2.2 R8.1 R10.1 U2.4 U2.5 | length 144
  Top Layer 1 w10: v3(2188.34,1512.49) U2.5@2188.34,1465.44 U2.4@2208.03,1465.44 ; v3(2256.77,1218.85) 2311.08,1218.85 2315.17,1222.93 2316.15,1222.93 2326.9,1233.68 C9.2@2326.9,1234.67
GATE: D4.1 Q3.1 U2.10 | length 1331.1
  Top Layer 1 w10: U2.10@2267.08,1290.24 2267.08,1269.08 2285.83,1250.33 v3(2285.83,1249.02)
  Bottom Layer 1 w10: 2285.83,1135.85 v3(2285.83,1249.02)
  Bottom Layer 1 w15: D4.1@2228.06,1037.6 D4.1@2228.22,1037.77 ; 2228.22,1078.24 2285.83,1135.85
  Bottom Layer 1 w20: D4.1@2228.06,1037.6 2228.06,872.49 2271.78,828.77 2685.15,828.77 2722.8,866.41 2722.8,1088.89 2670.79,1140.9 Q3.1@2613.67,1140.9 ; D4.1@2228.22,1037.77 2228.22,1078.24
NetC1_1: C1.1 C2.1 D1.1 D2.1 J2.1 R1.1 TP4.1 U1.3 U1.4 U1.10 | length 1779
  Top Layer 1 w20: v3(2090.17,1308.69) 2121.25,1308.69
  Top Layer 1 w30: v2(1712.85,1386.99) 1713.61,1386.22 1759.25,1386.22 1792.15,1353.32 1792.15,1206.72 1824.57,1174.3 2115.25,1174.3 2138.9,1197.95 2138.9,1291.04 2121.25,1308.69
  Signal Layer w10: v2(1712.85,1386.99) 1758.48,1386.99 1812.43,1333.04 1812.43,748.77 J2.1@1812.43,511.6
  Bottom Layer 1 w10: U1.4@2056.31,1298.92 2080.4,1298.92 v3(2090.17,1308.69) 2090.17,1309.98 2081.54,1318.61 U1.3@2056.31,1318.61
NetC2_2: C2.2 U1.11 | length 79.4
  Bottom Layer 1 w10: C2.2@1885.81,1374.18 1885.81,1368.27 1915.79,1338.29 U1.11@1946.86,1338.29
NetC7_1: C7.1 D3.2 D5.2 | length 380
  Top Layer 1 w30: D5.2@1606.65,1048.09 1607.55,1305.48 D3.2@1608.79,1306.72 ; D5.2@1607.55,1051.3 1634.3,1024.55 C7.1@1717.28,1024.55
NetC8_1: C8.1 D1.2 Q1.3 Q2.2 Q2.3 Q2.4 TP2.1 U1.2 U1.9 | length 583.5
  Top Layer 1 w10: v1(1850.02,1444.88) 1878.76,1416.14 D1.2@1878.76,1339.91 1885.58,1333.1 1885.58,1324.23 v3(1916.53,1293.28)
  Signal Layer w10: v3(1916.53,1293.28) 1975.02,1234.79 2035.64,1234.79 2056.31,1255.46 2056.31,1318.61 2078.62,1340.91 2099.86,1340.91 v3(2101,1342.06)
  Bottom Layer 1 w10: v3(1916.53,1293.28) 1918.15,1293.28 1923.72,1298.84 1946.78,1298.84 U1.9@1946.86,1298.92 ; U1.2@2063.51,1338.29 2095.61,1338.29 2099.38,1342.06 v3(2101,1342.06) ; v3@2099.74,1341.23 2101.8,1341.23 2108.7,1348.13 2137.76,1348.13 C8.1@2138.9,1346.98
  other v1: 2046.33,1424.22 2046.33,1471.22 2046.33,1518.23 2046.33,1565.24 2046.33,1612.24 1845.07,1670.01 1895.43,1670.01 1945.79,1670.01 1996.16,1670.01 2046.52,1670.01 1845.07,1720.17 1895.43,1720.17 1945.79,1720.17 1996.16,1720.17 2046.52,1720.17 1845.07,1770.34 1895.43,1770.34 1945.79,1770.34 1996.16,1770.34 1845.07,1820.51 1895.43,1820.51 1945.79,1820.51 1996.16,1820.51 1845.07,1870.68 1895.43,1870.68 1945.79,1870.68 1996.16,1870.68 1845.07,1920.85 1895.43,1920.85 1945.79,1920.85 1996.16,1920.85 1845.07,2062.18 1895.43,2062.18 1945.79,2062.18 1996.16,2062.18
NetC14_1: C14.1 U2.6 | length 83.2
  Top Layer 1 w10: v3(2175.67,1240.14) 2176.82,1241.29 2176.82,1257.56 2188.34,1269.08 U2.6@2188.34,1290.24
  Bottom Layer 1 w10: v3(2175.67,1240.14) 2175.67,1238.52 2181.88,1232.32 2181.88,1223.69 2186.72,1218.85 C14.1@2188.69,1218.85
NetC15_1: C15.1 R3.2 | length 43.8
  Top Layer 1 w20: R3.2@1839.27,1274.97 C15.1@1839.39,1231.17
NetJ2_2: J2.2 U1.6 | length 835.6
  Signal Layer w10: J2.2@1912.43,511.6 1912.43,857.34 2045.54,990.45 2045.54,1209.22 2079.25,1242.93 2079.25,1248.19 v3(2080.4,1249.34)
  Bottom Layer 1 w10: U1.6@2056.31,1259.55 2070.19,1259.55 v3(2080.4,1249.34)
NetQ1_1: Q1.1 R3.1 TP6.1 U1.8 | length 404.5
  Top Layer 1 w20: R3.1@1878.8,1274.81 R3.1@1878.64,1274.97 1898.23,1274.81 1910.46,1262.58 1927.02,1262.58 1942.53,1278.09 1942.53,1460.69 1918.39,1484.83 Q1.1@1918.39,1559.03
  Bottom Layer 1 w10: v3(1916.1,1262.58) 1916.1,1263.14 1932.11,1279.16 1946.78,1279.16 U1.8@1946.86,1279.23
NetQ2_1: Q2.1 TP5.1 U1.1 | length 1066.9
  Top Layer 1 w10: Q2.1@2051.57,2035.41 Q2.1@2051.88,2035.71 ; v2@2051.88,2104.74 v2(2052.18,2105.05)
  Top Layer 1 w30: Q2.1@2051.88,2035.71 v2@2051.88,2104.74
  Bottom Layer 1 w10: U1.1@2056.31,1357.98 2081.34,1357.98 2113.97,1390.6
  Bottom Layer 1 w20: 2113.97,1390.6 2113.97,2043.26 v2(2052.18,2105.05) 2052.18,2198.45 TP5.1@2117.53,2263.8
NetQ3_5: Q3.5 R5.2 U2.1 | length 230
  Top Layer 1 w10: U2.1@2267.08,1465.44 2266.73,1465.78 2266.73,1487.73 2266.3,1488.17 2266.3,1498.98 2293.29,1525.96 2400.07,1525.96 2409.15,1516.88 R5.2@2409.15,1478.57
  other v1: 2326.41,1305.48 2373.58,1305.48 2419.38,1305.48 2465.18,1305.48 2326.41,1360.3 2373.58,1360.3 2419.38,1360.3 2465.18,1360.3 2419.38,1415.13 2465.18,1415.13 2510.99,1414.82
  other v5: 2510.99,1305.48 2510.99,1360.3
NetR10_2: R10.2 U2.7 | length 100.7
  Top Layer 1 w10: v3(2197.97,1249.02) 2197.97,1250.64 2207.68,1260.35 2207.68,1289.9 U2.7@2208.03,1290.24
  Bottom Layer 1 w10: v3(2197.97,1249.02) 2221.19,1272.24 R10.2@2221.19,1294.74
OV: R2.1 R4.2 U1.5 | length 488.2
  Top Layer 1 w10: v3(2208.03,1602.12) R2.1@2208.03,1630.64
  Signal Layer w10: v3(2089.02,1279.23) 2117.53,1279.23 2152.46,1314.16 2152.46,1546.55 v3(2208.03,1602.12)
  Bottom Layer 1 w10: U1.5@2056.31,1279.23 v3(2089.02,1279.23) 2090.17,1278.09 2099.37,1278.09 2117.24,1260.21 R4.2@2117.24,1258.25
